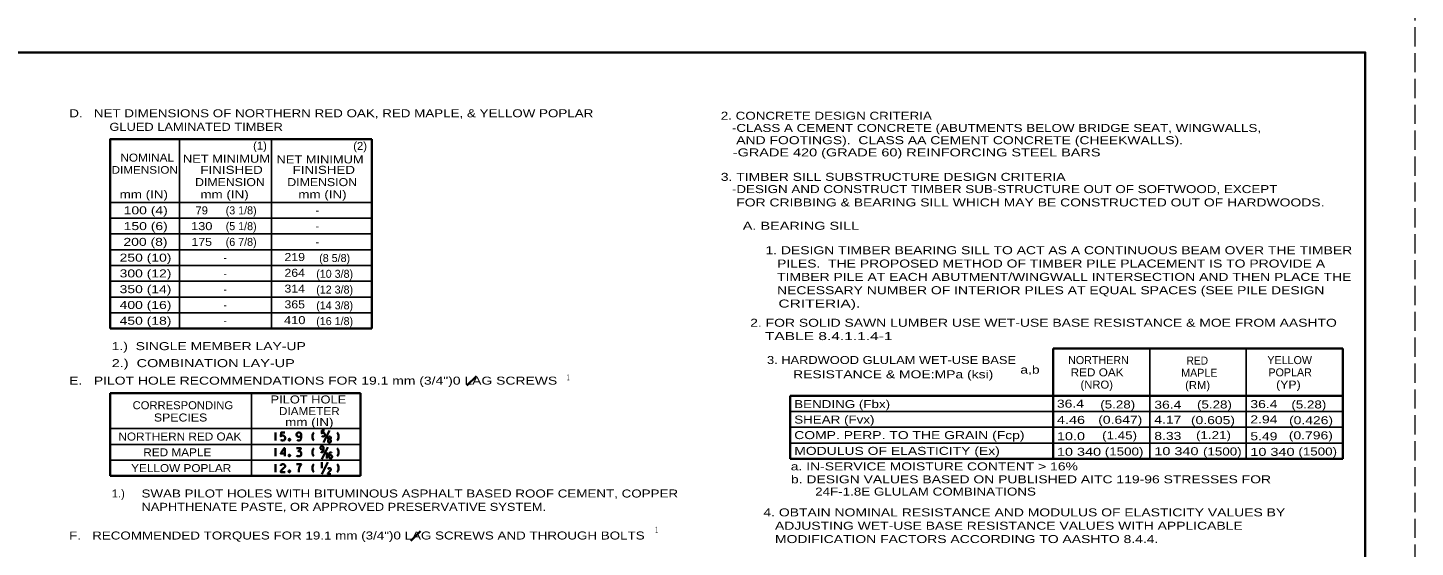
# Model space of a CAD drawing. Extents: x 0 to 68, y -44 to 0.
# Drawn here: x 47.19 to 68, y -30.17 to -22.38 of the extents above; entities that cross this region are included whole.
import ezdxf
from ezdxf.enums import TextEntityAlignment as Align

# ---------------------------------------------------------------- set-up
doc = ezdxf.new("R2010")
doc.units = 0
doc.header["$LTSCALE"] = 0.048
doc.linetypes.add('LONG_DASHED', pattern=[7.5, 6, -1.5])
for name, color, linetype, lineweight in [('1', 7, 'Continuous', 25), ('2', 7, 'Continuous', 35), ('53', 7, 'Continuous', 35), ('63', 7, 'LONG_DASHED', 13)]:
    doc.layers.add(name, color=color, linetype=linetype, lineweight=lineweight)

msp = doc.modelspace()

# ---------------------------------------------------------------- linework, layer by layer
at = {"layer": '1', "lineweight": 35}
msp.add_lwpolyline([(35.75, -43.25), (67.25, -43.25), (67.25, -22.75), (35.75, -22.75)], close=True, dxfattribs=at)
at = {"layer": '2', "lineweight": 25}
for p, q in [((49.46783, -24.05208), (49.46783, -26.89275)), ((50.851, -24.05208), (50.851, -26.89275)), ((49.46783, -24.29125), (49.46783, -25.94675)), ((52.35492, -25.00075), (48.42892, -25.00075)), ((52.35492, -25.23725), (48.42892, -25.23725)), ((52.35492, -25.47375), (48.42892, -25.47375)), ((52.35492, -25.71025), (48.42892, -25.71025)), ((52.35492, -25.94675), (48.42892, -25.94675)), ((52.35492, -26.18325), (48.42892, -26.18325)), ((52.35492, -26.41975), (48.42892, -26.41975)), ((52.35492, -26.65625), (48.42892, -26.65625)), ((64.02083, -27.19), (64.02083, -28.8455)), ((65.46375, -27.19), (65.46375, -28.8455)), ((50.54683, -27.86025), (50.54683, -29.10233)), ((66.91192, -28.136), (58.6245, -28.136)), ((52.18583, -28.39283), (48.42892, -28.39283)), ((66.91192, -28.3725), (58.6245, -28.3725)), ((52.18583, -28.62933), (48.42892, -28.62933)), ((66.91192, -28.609), (58.6245, -28.609)), ((52.18583, -28.86583), (48.42892, -28.86583))]:
    msp.add_line(p, q, dxfattribs=at)
at = {"layer": '2'}
for p, q in [((52.35492, -24.05208), (52.35492, -26.89275)), ((52.35492, -26.89275), (48.42892, -26.89275)), ((62.56842, -27.19), (62.56842, -28.8455)), ((66.91192, -27.19), (62.56842, -27.19)), ((66.91192, -27.19), (66.91192, -28.8455)), ((53.92267, -27.60333), (53.78058, -27.74542)), ((52.18583, -27.86025), (48.42892, -27.86025)), ((48.42892, -27.86025), (48.42892, -29.10233)), ((52.18583, -27.86025), (52.18583, -29.10233)), ((66.91192, -27.8995), (58.6245, -27.8995)), ((58.6245, -27.8995), (58.6245, -28.8455)), ((50.90933, -28.57117), (50.90933, -28.45117)), ((51.62742, -28.60142), (51.71717, -28.42092)), ((50.90925, -28.80767), (50.90925, -28.68767)), ((51.60367, -28.84925), (51.6925, -28.66875)), ((51.6015, -28.98367), (51.6015, -28.89392)), ((51.60525, -29.07442), (51.695, -28.89392)), ((51.67933, -28.83792), (51.67933, -28.74817)), ((66.91192, -28.8455), (58.6245, -28.8455)), ((52.18583, -29.10233), (48.42892, -29.10233)), ((50.90892, -29.04417), (50.90892, -28.92417)), ((53.08158, -29.93117), (52.9395, -30.07325))]:
    msp.add_line(p, q, dxfattribs=at)
for points in [[(52.35492, -24.05208), (48.42892, -24.05208), (48.42892, -26.89275)], [(51.051, -28.45117), (50.99242, -28.45117), (50.98775, -28.50783), (51.01042, -28.4975), (51.0265, -28.4975), (51.04158, -28.50317), (51.051, -28.5135), (51.05575, -28.52767), (51.05575, -28.54283), (51.051, -28.55792), (51.04158, -28.56742), (51.02083, -28.57117), (51.00658, -28.57117), (50.99625, -28.56742), (50.98775, -28.557)], [(51.29483, -28.49467), (51.27967, -28.50975), (51.26458, -28.51542), (51.25508, -28.51633), (51.24092, -28.50975), (51.23058, -28.50033), (51.22583, -28.48517), (51.22583, -28.48042), (51.22958, -28.46442), (51.24, -28.45592), (51.25508, -28.45117), (51.26458, -28.45117), (51.27875, -28.45592), (51.29008, -28.46442), (51.29483, -28.48042), (51.29483, -28.51542), (51.29292, -28.52767), (51.28917, -28.55417), (51.28442, -28.56267), (51.27875, -28.56742), (51.26458, -28.57117), (51.25508, -28.57117), (51.24092, -28.56742), (51.23525, -28.56267)], [(51.48192, -28.57117), (51.47433, -28.55892), (51.46867, -28.54567), (51.46492, -28.53242), (51.463, -28.51825), (51.463, -28.50408), (51.46492, -28.48992), (51.46867, -28.47667), (51.47433, -28.46342), (51.48192, -28.45117)], [(51.64442, -28.42092), (51.60567, -28.42092), (51.60283, -28.46342), (51.61792, -28.45492), (51.62833, -28.45492), (51.63875, -28.45967), (51.64442, -28.46725), (51.64725, -28.47758), (51.64725, -28.489), (51.64442, -28.50033), (51.63875, -28.50783), (51.62458, -28.51067), (51.61508, -28.51067), (51.6085, -28.50783), (51.60283, -28.50033)], [(51.83575, -28.57117), (51.84325, -28.55892), (51.84892, -28.54567), (51.85275, -28.53242), (51.85458, -28.51825), (51.85458, -28.50408), (51.85275, -28.48992), (51.84892, -28.47667), (51.84325, -28.46342), (51.83575, -28.45117)], [(51.05567, -28.76608), (50.98767, -28.76608), (50.98767, -28.76133), (51.04058, -28.68767), (51.04717, -28.68767), (51.04717, -28.80767)], [(51.22575, -28.68767), (51.28908, -28.68767), (51.28525, -28.70183), (51.27867, -28.71225), (51.26925, -28.72167), (51.25033, -28.73117), (51.2645, -28.73117), (51.27958, -28.73775), (51.28908, -28.74717), (51.29375, -28.76233), (51.29375, -28.77842), (51.28908, -28.79442), (51.27867, -28.80392), (51.2645, -28.80767), (51.24842, -28.80767), (51.23425, -28.80392), (51.22575, -28.7935)], [(51.48183, -28.80767), (51.47425, -28.79542), (51.46858, -28.78217), (51.46483, -28.76892), (51.46292, -28.75475), (51.46292, -28.74058), (51.46483, -28.72642), (51.46858, -28.71317), (51.47425, -28.69992), (51.48183, -28.68767)], [(51.62825, -28.68958), (51.61883, -28.70092), (51.60842, -28.70558), (51.60183, -28.70558), (51.59233, -28.70092), (51.58575, -28.69425), (51.58292, -28.68292), (51.58292, -28.67917), (51.58575, -28.66692), (51.59233, -28.66025), (51.60183, -28.65742), (51.60842, -28.65742), (51.61783, -28.66025), (51.62542, -28.66692), (51.62825, -28.67917), (51.62825, -28.70558), (51.62642, -28.71408), (51.6245, -28.734), (51.62167, -28.74058), (51.61783, -28.74433), (51.60842, -28.74717), (51.60183, -28.74717), (51.59233, -28.74433), (51.5895, -28.74058)], [(51.72283, -28.55133), (51.73133, -28.5485), (51.73508, -28.54375), (51.737, -28.53333), (51.737, -28.52867), (51.73508, -28.51733), (51.73042, -28.5145), (51.71808, -28.51167), (51.70492, -28.5145), (51.70208, -28.51733), (51.69825, -28.52867), (51.69825, -28.53333), (51.70108, -28.54375), (51.70492, -28.5485), (51.71433, -28.55133), (51.72283, -28.55133), (51.73133, -28.557), (51.737, -28.5655), (51.74083, -28.57492), (51.74083, -28.57875), (51.73792, -28.591), (51.73133, -28.59858), (51.72283, -28.60142), (51.71433, -28.60142), (51.70492, -28.59858), (51.69825, -28.591), (51.69642, -28.57967), (51.69642, -28.57492), (51.69925, -28.5655), (51.70492, -28.557), (51.71433, -28.55133)], [(51.83567, -28.80767), (51.84317, -28.79542), (51.84883, -28.78217), (51.85267, -28.76892), (51.8545, -28.75475), (51.8545, -28.74058), (51.85267, -28.72642), (51.84883, -28.71317), (51.84317, -28.69992), (51.83567, -28.68767)], [(51.75108, -28.75383), (51.74733, -28.751), (51.73975, -28.74817), (51.73217, -28.74817), (51.72275, -28.751), (51.71142, -28.76608), (51.7095, -28.78025), (51.7095, -28.79633), (51.7105, -28.80958), (51.71617, -28.8275), (51.72275, -28.83508), (51.73217, -28.83792), (51.74825, -28.83408), (51.75492, -28.8275), (51.75775, -28.81617), (51.75775, -28.8105), (51.75492, -28.802), (51.74825, -28.7935), (51.73783, -28.79067), (51.73125, -28.78975), (51.72183, -28.7935), (51.71617, -28.802), (51.71233, -28.81617)], [(50.98733, -28.94875), (50.99108, -28.93742), (51.0015, -28.92792), (51.01567, -28.92417), (51.02608, -28.92417), (51.04025, -28.92792), (51.05058, -28.93833), (51.05533, -28.94875), (51.05533, -28.95917), (51.05158, -28.96767), (51.02792, -28.98558), (50.99108, -29.02342), (50.98733, -29.03283), (50.98733, -29.04417), (51.05533, -29.04417)], [(51.22542, -28.92417), (51.29342, -28.92417), (51.29342, -28.92892), (51.27267, -28.95917), (51.26417, -28.98275), (51.25942, -29.012), (51.25942, -29.04417)], [(51.4815, -29.04417), (51.47392, -29.03192), (51.46825, -29.01867), (51.4645, -29.00542), (51.46258, -28.99125), (51.46258, -28.97708), (51.4645, -28.96292), (51.46825, -28.94967), (51.47392, -28.93642), (51.4815, -28.92417)], [(51.695, -29.00258), (51.69692, -28.99408), (51.7035, -28.9875), (51.71392, -28.98467), (51.7205, -28.98467), (51.73, -28.9875), (51.73658, -28.995), (51.73942, -29.00258), (51.73942, -29.01017), (51.73658, -29.01675), (51.7215, -29.03), (51.69692, -29.05833), (51.695, -29.06592), (51.695, -29.07442), (51.73942, -29.07442)], [(51.83533, -29.04417), (51.84283, -29.03192), (51.8485, -29.01867), (51.85233, -29.00542), (51.85417, -28.99125), (51.85417, -28.97708), (51.85233, -28.96292), (51.8485, -28.94967), (51.84283, -28.93642), (51.83533, -28.92417)]]:
    msp.add_lwpolyline(points, dxfattribs=at)
for points in [[(51.13042, -28.55892), (51.12942, -28.55417), (51.12658, -28.55042), (51.12283, -28.54758), (51.11808, -28.54658), (51.11342, -28.54758), (51.10958, -28.55042), (51.10675, -28.55417), (51.10583, -28.55892), (51.10675, -28.56358), (51.10958, -28.56742), (51.11342, -28.57025), (51.11808, -28.57117), (51.12283, -28.57025), (51.12658, -28.56742), (51.12942, -28.56358)], [(51.13033, -28.79542), (51.12933, -28.79067), (51.1265, -28.78692), (51.12275, -28.78408), (51.118, -28.78308), (51.11333, -28.78408), (51.1095, -28.78692), (51.10667, -28.79067), (51.10575, -28.79542), (51.10667, -28.80008), (51.1095, -28.80392), (51.11333, -28.80675), (51.118, -28.80767), (51.12275, -28.80675), (51.1265, -28.80392), (51.12933, -28.80008)], [(51.13, -29.03192), (51.129, -29.02717), (51.12617, -29.02342), (51.12242, -29.02058), (51.11767, -29.01958), (51.113, -29.02058), (51.10917, -29.02342), (51.10633, -29.02717), (51.10542, -29.03192), (51.10633, -29.03658), (51.10917, -29.04042), (51.113, -29.04325), (51.11767, -29.04417), (51.12242, -29.04325), (51.12617, -29.04042), (51.129, -29.03658)]]:
    msp.add_lwpolyline(points, close=True, dxfattribs=at)
at = {"layer": '63'}
msp.add_lwpolyline([(34, -44), (68, -44), (68, -22), (34, -22)], close=True, dxfattribs=at)

# ---------------------------------------------------------------- texts
at = {"layer": '2'}
for s, height, width, p in [('D.   NET DIMENSIONS OF NORTHERN RED OAK, RED MAPLE, & YELLOW POPLAR', 0.12, 1.25, (47.81758, -23.72358)), ('GLUED LAMINATED TIMBER', 0.12, 1.2, (48.419, -23.92683)), ('(1)', 0.12, 1.05, (50.573, -24.20925)), ('(2)', 0.12, 1.05, (52.07492, -24.213)), ('1.)  SINGLE MEMBER LAY-UP', 0.12, 1.3, (48.4535, -27.2155)), ('2.)  COMBINATION LAY-UP', 0.12, 1.35, (48.4535, -27.4705)), ('3. HARDWOOD GLULAM WET-USE BASE', 0.12, 1.2, (58.27933, -27.42367)), ('a,b', 0.12, 1.3, (62.07783, -27.56775)), ('E.   PILOT HOLE RECOMMENDATIONS FOR 19.1 mm (3/4")0 LAG SCREWS', 0.12, 1.3, (47.81442, -27.73275)), ('1', 0.09, 0.45, (55.27958, -27.66592)), ('RESISTANCE & MOE:MPa (ksi)', 0.12, 1.3, (58.67083, -27.63742)), ('BENDING (Fbx)', 0.12, 1.25, (58.68758, -28.08417)), ('36.4', 0.12, 1.3, (62.6265, -28.07833)), ('(5.28)', 0.12, 1.25, (63.27667, -28.09025)), ('36.4', 0.12, 1.3, (64.08717, -28.0935)), ('(5.28)', 0.12, 1.25, (64.727, -28.09025)), ('36.4', 0.12, 1.3, (65.5275, -28.08458)), ('(5.28)', 0.12, 1.25, (66.14225, -28.09025)), ('SHEAR (Fvx)', 0.12, 1.25, (58.68758, -28.31683)), ('4.46', 0.12, 1.35, (62.6265, -28.322)), ('(0.647)', 0.12, 1.3, (63.24608, -28.31925)), ('4.17', 0.12, 1.3, (64.08717, -28.31775)), ('(0.605)', 0.12, 1.3, (64.63625, -28.32533)), ('2.94', 0.12, 1.3, (65.5275, -28.31367)), ('(0.426)', 0.12, 1.3, (66.10683, -28.32667)), ('COMP. PERP. TO THE GRAIN (Fcp)', 0.12, 1.3, (58.68758, -28.54958)), ('10.0', 0.12, 1.35, (62.6265, -28.56567)), ('(1.45)', 0.12, 1.25, (63.30433, -28.55333)), ('8.33', 0.12, 1.3, (64.08717, -28.56142)), ('(1.21)', 0.12, 1.25, (64.71242, -28.54892)), ('5.49', 0.12, 1.3, (65.5275, -28.56708)), ('(0.796)', 0.12, 1.3, (66.10425, -28.55292)), ('MODULUS OF ELASTICITY (Ex)', 0.12, 1.3, (58.68758, -28.78608)), ('10 340', 0.12, 1.35, (62.6265, -28.79967)), ('(1500)', 0.12, 1.25, (63.34433, -28.79533)), ('10 340', 0.12, 1.35, (64.08717, -28.79058)), ('(1500)', 0.12, 1.25, (64.81708, -28.79533)), ('10 340', 0.12, 1.35, (65.5275, -28.80108)), ('(1500)', 0.12, 1.25, (66.24742, -28.79533)), ('a. IN-SERVICE MOISTURE CONTENT > 16%', 0.12, 1.3, (58.63567, -29.01875)), ('b. DESIGN VALUES BASED ON PUBLISHED AITC 119-96 STRESSES FOR', 0.12, 1.3, (58.6385, -29.21267)), ('1.)', 0.12, 1.05, (48.4535, -29.42517)), ('SWAB PILOT HOLES WITH BITUMINOUS ASPHALT BASED ROOF CEMENT, COPPER', 0.12, 1.25, (48.89992, -29.42517)), ('24F-1.8E GLULAM COMBINATIONS', 0.12, 1.25, (59.00167, -29.3965)), ('NAPHTHENATE PASTE, OR APPROVED PRESERVATIVE SYSTEM.', 0.12, 1.2, (48.89992, -29.62517)), ('F.   RECOMMENDED TORQUES FOR 19.1 mm (3/4")0 LAG SCREWS AND THROUGH BOLTS', 0.12, 1.25, (47.81442, -30.05517)), ('1', 0.09, 0.45, (56.60417, -29.95117))]:
    msp.add_text(s, height=height, dxfattribs=dict(at, width=width)).set_placement(p)
for s, height, width, p in [('NOMINAL', 0.12, 1.1, (48.98525, -24.38817)), ('NET MINIMUM', 0.12, 1.2, (50.17371, -24.40508)), ('NET MINIMUM', 0.12, 1.2, (51.57721, -24.41525)), ('DIMENSION', 0.114, 1.15, (48.94842, -24.5695)), ('FINISHED', 0.12, 1.25, (50.25037, -24.57192)), ('FINISHED', 0.12, 1.25, (51.63354, -24.57192)), ('DIMENSION', 0.12, 1.15, (50.22612, -24.75575)), ('DIMENSION', 0.12, 1.15, (51.60929, -24.75575)), ('mm (IN)', 0.12, 1.25, (48.93442, -24.9395)), ('mm (IN)', 0.12, 1.25, (50.14542, -24.9395)), ('mm (IN)', 0.12, 1.25, (51.61325, -24.9395)), ('100 (4)', 0.12, 1.3, (48.96308, -25.17892)), ('79', 0.12, 1.05, (49.80271, -25.17967)), ('150 (6)', 0.12, 1.3, (48.96308, -25.41542)), ('130', 0.12, 1.2, (49.80279, -25.41617)), ('200 (8)', 0.12, 1.3, (48.95958, -25.65192)), ('175', 0.12, 1.15, (49.80275, -25.65267)), ('250 (10)', 0.12, 1.3, (48.96008, -25.88842)), ('219', 0.12, 1.15, (51.19738, -25.87958)), ('300 (12)', 0.12, 1.3, (48.96008, -26.12492)), ('264', 0.12, 1.15, (51.19742, -26.11608)), ('350 (14)', 0.12, 1.3, (48.96008, -26.36142)), ('314', 0.12, 1.15, (51.19742, -26.35258)), ('400 (16)', 0.12, 1.3, (48.96008, -26.59792)), ('365', 0.12, 1.15, (51.19742, -26.58908)), ('450 (18)', 0.12, 1.3, (48.96008, -26.83442)), ('410', 0.12, 1.2, (51.19746, -26.82558)), ('RED', 0.12, 0.95, (64.73196, -27.43158)), ('RED OAK', 0.12, 1.1, (63.22892, -27.6085)), ('(NRO)', 0.12, 1.05, (63.22383, -27.79225)), ('(YP)', 0.12, 1.15, (66.09783, -27.79225)), ('(RM)', 0.12, 1.05, (64.73658, -27.79917)), ('CORRESPONDING', 0.12, 1.05, (49.51987, -28.10183)), ('PILOT HOLE', 0.12, 1.2, (51.40225, -28.01517)), ('DIAMETER', 0.12, 1.1, (51.41662, -28.18975)), ('SPECIES', 0.12, 1.15, (49.4855, -28.28567)), ('mm (IN)', 0.12, 1.25, (51.41608, -28.35375)), ('NORTHERN RED OAK', 0.12, 1.1, (49.4755, -28.57108)), ('RED MAPLE', 0.12, 1.1, (49.43675, -28.80758)), ('YELLOW POPLAR', 0.12, 1.1, (49.49529, -29.04408))]:
    msp.add_text(s, height=height, dxfattribs=dict(at, width=width)).set_placement(p, align=Align.CENTER)
for s, p in [('(3 1/8)', (50.39408, -25.17967)), ('-', (51.53733, -25.17892)), ('(5 1/8)', (50.39408, -25.41617)), ('-', (51.53733, -25.41542)), ('(6 7/8)', (50.39408, -25.65267)), ('-', (51.53733, -25.65192)), ('(8 5/8)', (51.79625, -25.894)), ('-', (50.15417, -25.88842)), ('(10 3/8)', (51.79625, -26.1305)), ('-', (50.15417, -26.12492)), ('-', (50.15417, -26.36142)), ('(12 3/8)', (51.79625, -26.367)), ('-', (50.15417, -26.59792)), ('(14 3/8)', (51.79625, -26.6035)), ('-', (50.15417, -26.83442)), ('(16 1/8)', (51.79625, -26.84)), ('NORTHERN', (63.24946, -27.42467)), ('YELLOW', (66.11704, -27.42467)), ('MAPLE', (64.76192, -27.61542)), ('POPLAR', (66.12387, -27.6085))]:
    msp.add_text(s, height=0.12, dxfattribs=at).set_placement(p, align=Align.CENTER)
at = {"layer": '53'}
for s, width, p in [('2. CONCRETE DESIGN CRITERIA', 1.25, (57.5865, -23.76033)), ('   -CLASS A CEMENT CONCRETE (ABUTMENTS BELOW BRIDGE SEAT, WINGWALLS, ', 1.25, (57.5865, -23.94367)), ('    AND FOOTINGS).  CLASS AA CEMENT CONCRETE (CHEEKWALLS).', 1.3, (57.5865, -24.127)), ('   -GRADE 420 (GRADE 60) REINFORCING STEEL BARS', 1.35, (57.5865, -24.31033)), ('3. TIMBER SILL SUBSTRUCTURE DESIGN CRITERIA', 1.3, (57.5865, -24.677)), ('   -DESIGN AND CONSTRUCT TIMBER SUB-STRUCTURE OUT OF SOFTWOOD, EXCEPT', 1.25, (57.5865, -24.86033)), ('    FOR CRIBBING & BEARING SILL WHICH MAY BE CONSTRUCTED OUT OF HARDWOODS. ', 1.3, (57.5865, -25.06033)), ('A. BEARING SILL', 1.35, (57.9165, -25.41033)), ('1. DESIGN TIMBER BEARING SILL TO ACT AS A CONTINUOUS BEAM OVER THE TIMBER', 1.3, (58.25658, -25.777)), ('   PILES.  THE PROPOSED METHOD OF TIMBER PILE PLACEMENT IS TO PROVIDE A', 1.3, (58.25658, -25.977)), ('   TIMBER PILE AT EACH ABUTMENT/WINGWALL INTERSECTION AND THEN PLACE THE', 1.3, (58.25658, -26.177)), ('   NECESSARY NUMBER OF INTERIOR PILES AT EQUAL SPACES (SEE PILE DESIGN', 1.3, (58.25658, -26.377)), ('   CRITERIA). ', 1.45, (58.25658, -26.577)), ('    2. FOR SOLID SAWN LUMBER USE WET-USE BASE RESISTANCE & MOE FROM AASHTO', 1.3, (57.795, -26.86483)), ('       TABLE 8.4.1.1.4-1 ', 1.45, (57.795, -27.06483)), (' 4. OBTAIN NOMINAL RESISTANCE AND MODULUS OF ELASTICITY VALUES BY', 1.3, (58.1675, -29.70858)), ('    ADJUSTING WET-USE BASE RESISTANCE VALUES WITH APPLICABLE', 1.3, (58.1675, -29.90858)), ('    MODIFICATION FACTORS ACCORDING TO AASHTO 8.4.4.', 1.3, (58.1675, -30.10858))]:
    msp.add_text(s, height=0.12, dxfattribs=dict(at, width=width)).set_placement(p)

doc.saveas('drawing.dxf')
